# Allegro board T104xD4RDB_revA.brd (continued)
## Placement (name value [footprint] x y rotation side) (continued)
C1023  0.1uF  [0402]  186.82 169.67 90 top
C1024  0.1uF  [0402]  187.96 160.27 270 top
C1025  0.1uF  [0402]  38.74 35.81 90 top
C1026  0.1uF  [0402]  170.18 142.24 0 top
C1027  0.1uF  [0402]  53.85 61.47 90 top
C1028  0.1uF  [0402]  51.44 52.96 90 top
C1029  0.1uF  [0402]  27.94 146.56 0 top
C1030  0.1uF  [0402]  34.04 148.34 0 top
C1031  4.7uF  [0603]  43.43 148.08 90 top
C1032  0.1uF  [0402]  44.45 143.26 0 top
C1033  0.1uF  [0402]  44.45 144.27 0 top
C1034  0.1uF  [0402]  28.19 44.45 0 top
C1035  10uF  [1206]  258.7 200.53 0 top
C1036  10uF  [1206]  258.7 171.96 0 top
C1037  10uF  [1206]  258.7 181.48 0 top
C1038  10uF  [1206]  258.7 191.01 0 top
C1039  10uF  [1206]  67.18 82.42 0 top
C1040  0.1uF  [0603]  63.12 81.91 180 top
C1041  100uF  [CAPE_B6D3]  20.57 49.91 90 top
C1042  10uF  [1206]  18.16 43.43 270 top
C1043  330uF  [CAPE_B8]  22.1 61.59 0 top
C1044  330uF  [CAPE_B8]  22.1 70.74 0 top
C1045  10uF  [0805]  6.22 39.75 180 top
C1046  0.1uF  [0402]  12.07 21.72 0 top
C1047  0.1uF  [0402]  14.48 22.73 0 top
C1048  0.1uF  [0402]  20.19 55.37 0 top
C1049  0.1uF  [0402]  5.59 24.26 0 top
C1050  0.1uF  [0402]  6.6 32.64 0 top
C1051  0.1uF  [0402]  7.62 26.16 270 top
C1052  0.1uF  [0402]  8.13 27.69 0 top
C1053  10uF  [0805]  9.14 25.4 270 top
C1054  0.1uF  [0402]  195.07 100.2 0 top
C1055  0.1uF  [0402]  195.07 101.47 0 top
C1065  22uF  [0805]  144.78 138.81 90 bottom
C1066  22uF  [0805]  151.13 138.81 90 bottom
C1067  0.1uF  [0402]  144.4 68.96 0 top
C1068  0.1uF  [0402]  139.7 68.2 270 top
C1069  0.1uF  [0402]  254.64 61.72 90 top
C1070  0.01uF  [0402]  242.57 38.1 270 top
C1071  0.1uF  [0402]  253.75 38.1 90 top
C1072  0.01uF  [0402]  251.46 38.1 270 top
C1073  0.01uF  [0402]  248.41 38.1 270 top
C1074  0.01uF  [0402]  245.49 38.1 270 top
C1075  1000pF  [1206]  240.67 20.7 90 bottom
C1076  0.1uF  [0402]  251.84 41.91 0 top
C1077  0.1uF  [0402]  251.84 42.93 0 top
C1078  1000pF  [1206]  251.33 28.19 270 bottom
C1079  470pF  [0402]  237.87 52.07 270 top
C1080  470pF  [0402]  236.86 54.1 270 top
C1081  1000pF  [1206]  240.67 28.19 270 bottom
C1082  4.7pF  [0402]  240.79 49.02 180 top
C1083  4.7pF  [0402]  240.79 48.01 180 top
C1084  1000pF  [0402]  239.65 44.58 180 bottom
C1085  22uF  [0805]  240.41 43.05 180 bottom
C1086  0.1uF  [0402]  238.76 43.43 90 top
C1087  0.1uF  [0402]  251.33 54.61 270 bottom
C1088  0.1uF  [0402]  244.48 54.99 0 bottom
C1089  0.1uF  [0402]  242.7 48.39 0 bottom
C1090  0.1uF  [0402]  253.24 46.86 90 bottom
C1091  0.1uF  [0402]  249.94 54.61 270 bottom
C1092  0.1uF  [0402]  249.81 46.86 90 bottom
C1093  0.1uF  [0402]  248.29 46.86 90 bottom
C1094  0.1uF  [0402]  244.98 46.86 90 bottom
C1095  0.1uF  [0402]  244.48 49.78 0 bottom
C1096  0.1uF  [0402]  251.71 46.86 90 bottom
C1097  0.1uF  [0402]  247.02 46.86 90 bottom
C1098  22uF  [0805]  240.16 46.35 180 top
C1099  0.1uF  [0402]  243.46 46.99 0 bottom
C1100  0.1uF  [0402]  246 46.86 90 bottom
C1101  0.1uF  [0402]  242.95 54.86 90 bottom
C1102  0.1uF  [0402]  252.6 52.58 180 bottom
C1103  0.1uF  [0402]  252.6 50.16 180 bottom
C1104  0.01uF  [0402]  266.83 38.1 270 top
C1105  0.1uF  [0402]  272.03 38.1 90 top
C1106  0.01uF  [0402]  269.88 38.1 270 top
C1107  0.01uF  [0402]  260.99 38.1 270 top
C1108  0.01uF  [0402]  263.91 38.1 270 top
C1109  1000pF  [1206]  259.08 20.7 90 bottom
C1110  0.1uF  [0402]  274.7 41.91 0 top
C1111  0.1uF  [0402]  274.7 42.93 0 top
C1112  1000pF  [1206]  259.08 28.19 270 bottom
C1113  470pF  [0402]  260.73 52.07 270 top
C1114  470pF  [0402]  259.72 54.1 270 top
C1115  1000pF  [1206]  269.75 28.19 270 bottom
C1116  4.7pF  [0402]  263.65 49.02 180 top
C1117  4.7pF  [0402]  263.65 48.01 180 top
C1118  1000pF  [0402]  262.51 44.58 180 bottom
C1119  22uF  [0805]  263.27 43.05 180 bottom
C1120  0.1uF  [0402]  272.67 46.86 90 bottom
C1121  0.1uF  [0402]  274.19 54.61 270 bottom
C1122  0.1uF  [0402]  267.34 54.99 0 bottom
C1123  0.1uF  [0402]  265.81 54.86 90 bottom
C1124  0.1uF  [0402]  276.1 46.86 90 bottom
C1125  0.1uF  [0402]  272.8 54.61 270 bottom
C1126  0.1uF  [0402]  267.34 49.78 0 bottom
C1127  0.1uF  [0402]  274.57 46.86 90 bottom
C1128  0.1uF  [0402]  261.62 43.43 90 top
C1129  0.1uF  [0402]  271.14 46.86 90 bottom
C1130  0.1uF  [0402]  269.88 46.86 90 bottom
C1131  0.1uF  [0402]  267.84 46.86 90 bottom
C1132  22uF  [0805]  263.02 46.35 180 top
C1133  0.1uF  [0402]  265.56 48.39 0 bottom
C1134  0.1uF  [0402]  266.32 46.99 0 bottom
C1135  0.1uF  [0402]  268.86 46.86 90 bottom
C1136  0.1uF  [0402]  275.46 50.16 180 bottom
C1137  0.1uF  [0402]  275.46 52.58 180 bottom
C1138  3000pF  [0402]  129.92 89.92 180 bottom
D1  GRN  [LED_0603]  91.95 77.47 0 top
D2  CMHD3595  [SOD123]  57.79 25.4 90 top
D3  CMHD3595  [SOD123]  66.93 31.24 0 top
D4  GRN  [LED_0603]  80.14 22.61 90 top
D5  GRN  [LED_PM_1S]  36.45 1.14 0 top
D6  GRN  [LED_PM_1S]  32.13 1.14 0 top
D7  RB521  [SOD523]  5.84 21.97 0 top
F1  1A  [1206]  19.18 38.23 270 top
F2  500mA  [1206]  258.7 195.83 0 top
F3  500mA  [1206]  258.7 176.78 0 top
F4  500mA  [1206]  258.7 186.31 0 top
F5  500mA  [1206]  258.7 205.36 0 top
FB1  BLM21PG121SN1  [0805]  66.8 19.56 90 top
FB2  BLM21PG121SN1  [0805]  75.44 20.45 90 top
FB3  BLM21PG121SN1  [0805]  64.77 20.07 90 top
FB4  BLM21PG121SN1  [0805]  73.41 19.94 90 top
FB5  BLM18PG121SN1  [0603]  130.3 85.85 270 bottom
FB6  BLM18PG121SN1  [0603]  128.14 86.61 0 bottom
FB7  BLM18PG121SN1  [0603]  125.22 86.61 180 bottom
FB8  BLM18BD601SN1  [0603]  105.54 28.32 0 top
FB9  BLM18BD601SN1  [0603]  105.54 25.53 0 top
FB10  BLM18BD601SN1  [0603]  105.54 26.92 0 top
FB11  BLM18BD601SN1  [0603]  105.54 29.72 0 top
FB12  BLM18BD601SN1  [0603]  105.54 24.13 0 top
FB13  BLM18BD601SN1  [0603]  105.54 21.34 0 top
FB14  BLM18BD601SN1  [0603]  105.54 22.73 0 top
FB15  BLM18BD601SN1  [0603]  105.54 31.11 0 top
FB16  BLM18PG121SN1  [0603]  97.03 29.21 90 top
FB17  BLM18PG121SN1  [0603]  88.52 31.5 180 bottom
FB18  BLM18PG121SN1  [0603]  68.45 58.29 0 bottom
FB20  BLM18BD601SN1  [0603]  150.88 37.97 270 top
FB21  BLM18BD601SN1  [0603]  153.42 38.48 0 top
FB22  BLM18PG121SN1  [0603]  179.58 90.04 90 top
FB23  BLM18PG121SN1  [0603]  177.67 83.69 90 top
FB24  BLM18PG121SN1  [0603]  211.33 90.04 90 top
FB25  BLM18PG121SN1  [0603]  209.42 83.69 90 top
FB26  BLM18BD601SN1  [0603]  239.01 60.71 180 top
FB37  BLM18BD601SN1  [0603]  28.19 129.29 0 top
FB38  BLM18BD601SN1  [0603]  28.19 137.41 0 top
FB39  BLM18BD601SN1  [0603]  28.19 121.16 0 top
FB40  BLM18BD601SN1  [0603]  25.02 100.71 180 top
FB41  BLM18BD601SN1  [0603]  204.47 102.62 180 top
FB42  BLM18PG221SN1  [0603]  235.08 128.4 270 bottom
FB43  BLM18PG221SN1  [0603]  235.08 125.48 270 bottom
FB44  BLM18BD601SN1  [0603]  255.02 38.61 270 top
FB45  BLM18BD601SN1  [0603]  273.43 38.35 270 top
FB46  BLM18PG121SN1  [0603]  95.38 17.91 270 top
J1  DDR4_DIMM  [CON_DDR4_DIMM]  130.05 164.97 0 top
J2  JMP3  [JMP_P254_T_1X3]  20.7 28.83 180 top
J3  SD_CARD_SKT  [CON_SD]  39.02 2.52 180 bottom
J4  HTST-108-01-L-DV  [HDR_P254_HTST_2X8]  10.54 117.35 0 top
J5  USB_A_2  [CON_USB_A_2]  69.02 -0.98 0 top
J6  JMP2  [JMP_P254_T_1X2]  65.91 145.8 270 top
J7  JMP2  [JMP_P254_T_1X2]  65.91 142.62 270 top
J8  JMP2  [JMP_P254_T_1X2]  65.91 148.97 270 top
J9  2XDB9  [DUALDB-9MM]  110.86 16.02 0 top
J10  BAT_SOCKET  [CON_BAT_WBA3B2]  56.01 155.7 180 top
J11  CONN_2X20  [CON_MEC6_120]  277.88 152.06 0 top
J12  HDMI_A  [CON_HDMI]  88.02 -0.98 0 top
J13  DF14-20P-1.25H  [CON_FPC_DF14_20P]  41.4 19.56 180 top
J14  HDR_1X2  [JMP_P254_T_1X2]  17.15 24.26 0 top
J15  HDR_1X2  [JMP_P254_T_1X2]  20.83 24.26 0 top
J16  CON_3PIN  [CON_WAFER_P254_S_1X3]  13.59 37.97 0 top
J17  CON_3PIN  [CON_WAFER_P254_S_1X3]  13.59 30.99 0 top
J18  JMP2  [JMP_P254_T_1X2]  249.94 171.83 270 top
J19  RJ45_LED_2X1  [CON_RJ45_2X1_LED]  142.86 -1.48 0 top
J20  RJ45_LED  [CON_RJ45_UP_1X1_LED]  161.36 -1.48 0 top
J21  RJ45_LED_8  [CON_RJ45_2X4_LED]  203.36 -1.48 0 top
J26  PCIE_X1  [CON_PEX1]  277.88 93.73 90 top
J27  MINIPCIE_CONN  [CON_MINIPCIE]  209.3 183.9 180 top
J28  MINIPCIE_CONN  [CON_MINIPCIE]  82.3 183.9 180 top
J29  SATA_CONN  [CON_SATA]  195.45 129.67 270 top
J30  CONN SKT 70  [CON2X35_SKT_0P8_SM]  225.17 143.64 90 top
J31  HDR_2X5  [HDR_P254_M_T_2X5]  24.38 83.19 180 top
J32  CON_3PIN  [CON_WAFER_P254_S_1X3]  264.54 193.42 90 top
J33  CON_3PIN  [CON_WAFER_P254_S_1X3]  264.54 174.37 90 top
J34  CON_3PIN  [CON_WAFER_P254_S_1X3]  264.54 183.9 90 top
J35  CON_3PIN  [CON_WAFER_P254_S_1X3]  264.54 202.95 90 top
J36  CON_3PIN  [CON_WAFER_P254_S_1X3]  64.01 77.34 180 top
J37  ATX_PWR_CONN_20PIN  [CON_ATX_20PIN]  10.54 63.88 270 top
J38  HDR_1X2  [JMP_P254_T_1X2]  20.07 17.02 0 top
J39  HDR_1X2  [JMP_P254_T_1X2]  15.75 17.02 0 top
J40  RJ45_LED  [CON_RJ45_UP_1X1_LED]  245.36 -1.48 0 top
J41  RJ45_LED  [CON_RJ45_UP_1X1_LED]  263.86 -1.48 0 top
J42  HDR_1X5  [HDR_P254_M_T_1X5]  244.09 165.48 90 top
L1  90ohm  [IND_CM_2012]  71.25 20.95 270 top
L2  90ohm  [IND_CM_2012]  68.96 20.95 270 top
L3  10uH  [0806]  240.54 165.74 0 top
L4  2.2uH  [IND_SWPA2520]  119.25 45.85 180 top
L5  2.2uH  [IND_SWPA2520]  137.16 53.85 180 top
L6  4.7uH  [IND_SWPA2520]  155.07 41.78 270 top
L7  1.0uH  [IND_IHLP_4040]  80.77 97.03 0 top
L9  2.2uH  [IND_IHLP_2525]  180.21 145.41 180 top
L10  3.3uH  [IND_IHLP_2525]  31.75 169.55 90 top
L11  3.3uH  [IND_IHLP_2525]  43.57 60.96 0 top
L12  4.7uH  [IND_IHLP_2525]  244.73 66.92 270 top
L13  2.2uH  [IND_IHLP_2525]  42.04 49.78 0 top
L15  2.2uH  [IND_IHLP_2525]  239.77 89.66 180 top
L17  4.7uH  [IND_SWPA2520]  240.67 43.69 270 top
L18  4.7uH  [IND_SWPA2520]  263.52 43.69 270 top
L19  90ohm  [IND_CM_2012]  92.58 14.35 270 top
L20  90ohm  [IND_CM_2012]  90.42 14.22 270 top
L21  90ohm  [IND_CM_2012]  88.27 14.22 270 top
L22  90ohm  [IND_CM_2012]  86.11 14.86 270 top
M2  MH  [MH_580S340P]  70.2 207.8 0 top
M3  MH  [MH_580S340P]  94.4 207.8 0 top
M4  MH  [MH_580S340P]  197.2 207.8 0 top
M5  MH  [MH_580S340P]  221.4 207.8 0 top
NOREF  val  [unnamed]  134.37 102.62 90 top
NOREF#2  -  [#2]  -252.98 -202.18 0 top
Q2  IRLML6346  [SOT23]  243.33 123.44 0 top
Q3  IRLML6346  [SOT23]  245.36 126.36 90 top
Q4  IRLML6346  [SOT23]  70.87 34.8 0 top
Q5  IRLML6346  [SOT23]  67.06 36.96 0 top
Q6  IRLML6346  [SOT23]  23.75 14.35 180 top
Q7  IRFH6200  [SO_8_FL]  93.85 105.28 270 bottom
Q8  IRLML6346  [SOT23]  93.85 104.9 270 top
Q9  IRFHM4226  [U8_FL]  35.05 36.83 0 top
Q10  IRFH6200  [SO_8_FL]  172.47 146.94 270 top
Q11  IRFHM4226  [U8_FL]  50.04 59.69 90 top
Q12  IRLML6346  [SOT23]  39.5 38.86 90 top
Q13  IRLML6346  [SOT23]  172.09 140.59 0 top
Q14  IRLML6346  [SOT23]  51.05 63.75 270 top
Q15  IRFH6200  [SO_8_FL]  49.78 48.77 90 top
Q16  IRLML2030  [SOT23]  36.96 144.4 0 top
Q17  IRLML2030  [SOT23]  40.64 144.4 0 top
Q18  IRLML6346  [SOT23]  48.9 53.85 270 top
Q19  IRLML2030  [SOT23]  40.64 148.46 0 top
Q20  IRLML2030  [SOT23]  36.96 148.46 0 top
Q21  IRLML6346  [SOT23]  32 144.53 270 top
Q22  IRLML6346  [SOT23]  31.12 148.46 0 top
Q23  IRF9321  [SO_8]  25.65 38.61 270 top
Q24  IRLML6346  [SOT23]  30.35 41.78 180 top
Q25  IRLML6346  [SOT23]  113.03 156.97 0 bottom
Q26  IRLML6346  [SOT23]  116.71 156.97 0 bottom
Q27  TP0610K  [SOT23]  63.25 84.45 270 top
Q28  IRLML6346  [SOT23]  58.17 83.82 0 top
Q29  MMBT4401  [SOT23]  6.22 35.18 0 top
Q30  IRFHM4226  [U8_FL]  250.83 62.74 0 top
Q31  IRLML6346  [SOT23]  255.02 64.9 270 top
R1  162  [0402]  136.77 114.32 270 bottom
R2  162  [0402]  133.57 114.32 270 bottom
R3  10K  [0402]  127.16 114.32 270 bottom
R4  0  [0402]  125.6 104.9 0 bottom
R5  1K  [0402]  109.47 160.27 90 top
R6  20K  [0402]  63.75 129.79 270 bottom
R7  20K  [0402]  65.02 129.79 270 bottom
R8  20K  [0402]  61.21 129.79 270 bottom
R9  4.7K  [0402]  58.55 130.56 270 bottom
R10  4.7K  [0402]  57.53 130.56 270 bottom
R11  4.7K  [0402]  54.48 130.56 270 bottom
R12  4.7K  [0402]  56.52 130.56 270 bottom
R13  20K  [0402]  62.48 129.79 270 bottom
R14  4.7K  [0402]  118.49 101.47 270 bottom
R15  4.7K  [0402]  55.5 130.56 270 bottom
R16  20K  [0402]  81.41 117.6 0 bottom
R17  20K  [0402]  67.56 129.79 90 bottom
R18  20K  [0402]  73.91 129.79 90 bottom
R19  20K  [0402]  72.64 129.79 90 bottom
R20  20K  [0402]  71.37 129.79 90 bottom
R21  22  [0402]  121.67 104.14 180 bottom
R22  4.7K  [0402]  81.41 116.59 0 bottom
R23  33  [0402]  91.31 113.92 180 bottom
R24  33  [0402]  91.31 114.94 180 bottom
R25  33  [0402]  89.28 115.44 180 bottom
R26  33  [0402]  91.31 115.95 180 bottom
R27  33  [0402]  91.31 116.97 180 bottom
R28  33  [0402]  89.28 117.47 180 bottom
R29  33  [0402]  91.31 117.98 180 bottom
R30  33  [0402]  89.28 118.49 180 bottom
R31  4.7K  [0402]  45.97 135.13 270 bottom
R32  33  [0402]  91.31 119 180 bottom
R33  4.7K  [0402]  47.24 135.13 270 bottom
R34  33  [0402]  91.31 120.02 180 bottom
R35  4.7K  [0402]  48.51 135.13 270 bottom
R36  33  [0402]  91.31 121.03 180 bottom
R37  4.7K  [0402]  49.78 135.13 270 bottom
R38  4.7K  [0402]  51.05 135.13 270 bottom
R39  4.7K  [0402]  52.32 135.13 270 bottom
R40  4.7K  [0402]  53.59 135.13 270 bottom
R41  4.7K  [0402]  54.86 135.13 270 bottom
R42  4.7K  [0402]  58.67 135.13 270 bottom
R43  4.7K  [0402]  59.94 135.13 270 bottom
R44  4.7K  [0402]  61.21 135.13 270 bottom
R45  4.7K  [0402]  62.48 135.13 270 bottom
R46  4.7K  [0402]  63.75 135.13 270 bottom
R47  4.7K  [0402]  66.29 135.13 270 bottom
R48  4.7K  [0402]  65.02 135.13 270 bottom
R49  4.7K  [0402]  67.56 135.13 270 bottom
R50  4.7K  [0402]  73.53 126.75 90 bottom
R51  4.7K  [0402]  86.87 121.79 180 bottom
R52  4.7K  [0402]  72.52 116.46 0 bottom
R53  4.7K  [0402]  64.77 125.22 0 bottom
R54  1K  [0402]  86.87 122.81 180 bottom
R55  4.7K  [0402]  86.87 120.78 180 bottom
R56  1K  [0402]  64.77 124.21 0 bottom
R57  4.7K  [0402]  267.34 145.16 180 top
R58  4.7K  [0402]  268.86 148.72 90 top
R59  4.7K  [0402]  257.56 145.29 0 top
R60  4.7K  [0402]  258.83 159 0 top
R61  33  [0402]  268.35 147.19 180 top
R62  4.7K  [0402]  270.76 148.21 180 top
R63  4.7K  [0402]  270.76 149.22 180 top
R64  51  [0402]  268.35 146.18 180 top
R65  10  [0402]  133.29 87.38 270 bottom
R66  51  [0402]  267.84 148.72 270 top
R67  0  [0402]  131.45 89.41 270 bottom
R68  10K  [0402]  32.13 38.23 90 bottom
R69  10K  [0402]  33.15 38.23 90 bottom
R70  10K  [0402]  46.1 38.23 90 bottom
R71  10K  [0402]  45.09 38.23 90 bottom
R72  10K  [0402]  34.16 38.23 90 bottom
R73  10K  [0402]  44.07 38.23 90 bottom
R74  10K  [0402]  43.05 38.23 90 bottom
R75  10K  [0402]  31.12 38.23 90 bottom
R78  4.7K  [0402]  52.96 101.22 0 bottom
R79  4.7K  [0402]  52.96 100.2 0 bottom
R80  4.7K  [0402]  121.54 95 180 bottom
R81  4.7K  [0402]  55.12 91.82 0 bottom
R82  4.7K  [0402]  121.54 91.95 180 bottom
R83  4.7K  [0402]  121.54 92.96 180 bottom
R84  4.7K  [0402]  139.32 90.17 270 bottom
R85  4.7K  [0402]  139.83 88.65 180 bottom
R86  4.7K  [0402]  140.34 90.17 270 bottom
R87  4.7K  [0402]  140.84 87.63 180 bottom
R88  4.7K  [0402]  133.41 89.41 270 bottom
R89  4.7K  [0402]  136.27 89.41 270 bottom
R90  4.7K  [0402]  55.12 94.87 0 bottom
R91  4.7K  [0402]  121.67 105.16 180 bottom
R92  1K  [0402]  54.48 99.95 90 bottom
R93  1K  [0402]  121.54 93.98 180 bottom
R94  4.7K  [0402]  55.12 92.84 0 bottom
R95  4.7K  [0402]  56.64 93.85 90 bottom
R96  4.7K  [0402]  248.54 126.24 0 top
R97  4.7K  [0402]  246.25 123.95 0 top
R98  4.7K  [0402]  248.54 127.25 0 top
R99  4.7K  [0402]  246.25 122.94 0 top
R100  4.7K  [0402]  137.29 89.41 270 bottom
R101  4.7K  [0402]  219.58 168.53 0 top
R102  4.7K  [0402]  138.3 89.41 270 bottom
R103  4.7K  [0402]  219.58 167.51 0 top
R104  4.7K  [0402]  48.01 102.62 180 bottom
R105  4.7K  [0402]  53.09 98.68 270 bottom
R106  4.7K  [0402]  55.12 93.85 180 bottom
R107  4.7K  [0402]  229.87 167.89 90 top
R108  4.7K  [0402]  134.37 89.41 90 bottom
R109  4.7K  [0402]  135.32 89.41 90 bottom
R110  4.7K  [0402]  97.79 77.41 270 top
R111  4.7K  [0402]  56.9 128.52 180 bottom
R112  510  [0402]  92.58 78.87 180 top
R113  698  [0402]  121.67 107.19 0 bottom
R114  698  [0402]  121.67 106.17 0 bottom
R115  10K  [0402]  97.54 126.75 0 top
R116  10  [0402]  18.92 112.27 0 top
R117  10K  [0402]  18.92 114.81 0 top
R118  10K  [0402]  18.92 113.54 180 top
R119  10K  [0402]  18.92 111 180 top
R120  10K  [0402]  18.92 108.58 180 top
R121  10K  [0402]  18.92 105.92 180 top
R122  10K  [0402]  18.92 103.38 180 top
R123  10K  [0402]  18.92 100.84 180 top
R124  10  [0402]  147.57 94.87 0 bottom
R125  10  [0402]  144.4 90.17 90 bottom
R126  10  [0402]  149.61 95.38 0 bottom
R127  10  [0402]  142.37 90.17 90 bottom
R128  10  [0402]  149.61 94.36 0 bottom
R129  10  [0402]  141.35 89.66 90 bottom
R130  10  [0402]  147.57 93.85 0 bottom
R131  4.7K  [0402]  146.81 92.08 0 bottom
R132  10  [0402]  145.92 89.92 0 bottom
R133  10  [0402]  143.38 90.17 90 bottom
R134  4.7K  [0402]  147.57 97.54 180 bottom
R135  10  [0402]  147.45 90.55 90 bottom
R136  10  [0402]  149.61 97.54 0 bottom
R137  10  [0402]  149.61 96.39 0 bottom
R138  10  [0402]  149.61 93.34 180 bottom
R139  1.5K  [0402]  124.97 57.91 270 top
R140  4.7K  [0402]  125.98 58.17 270 top
R142  4.7K  [0402]  155.58 95 180 bottom
R143  4.7K  [0402]  155.58 93.98 180 bottom
R144  4.7K  [0402]  155.58 92.96 180 bottom
R145  200  [0402]  140.77 99.81 270 bottom
R146  698  [0402]  148.08 109.73 180 bottom
R147  4.7K  [0402]  213.11 102.23 0 top
R148  4.7K  [0402]  219.71 118.11 0 top
R149  10K  [0402]  69.85 38.35 0 top
R150  10K  [0402]  69.85 37.34 0 top
R151  0  [0402]  65.41 33.4 0 top
R152  100K  [0402]  67.69 34.42 0 top
R153  100K  [0402]  67.69 33.4 0 top
R154  51.1K  [0402]  57.79 28.45 0 top
R155  0  [0402]  65.41 34.42 0 top
R156  1K  [0402]  61.34 37.47 270 top
R157  1K  [0402]  63.37 37.47 270 top
R158  51.1K  [0402]  69.98 31.24 90 top
R159  26.7K  [0402]  62.36 37.47 270 top
R160  18.2K  [0402]  57.79 29.46 180 top
R161  18.2K  [0402]  70.99 31.24 270 top
R162  0  [0402]  71.76 21.08 270 top
R163  0  [0402]  70.74 21.08 270 top
R164  0  [0402]  69.47 21.08 270 top
R165  0  [0402]  68.45 21.08 270 top
R166  10K  [0402]  123.57 89.92 0 bottom
R167  49.9  [0402]  123.57 87.88 0 bottom
R168  49.9  [0402]  122.56 90.93 0 bottom
R169  49.9  [0402]  122.05 89.41 270 bottom
R170  0  [0402]  132.4 89.41 270 bottom
R171  330  [0402]  68.2 145.67 90 top
R172  330  [0402]  68.2 142.49 90 top
R173  330  [0402]  68.2 148.84 90 top
R174  5.1  [0402]  121.41 97.92 0 bottom
R175  0.33  [0402]  159.13 112.65 0 bottom
R176  0  [0402]  159.13 113.66 0 bottom
R177  5.1  [0402]  121.41 100.46 0 bottom
R178  0.33  [0402]  159.13 116.46 0 bottom
R179  0  [0402]  159.13 117.47 0 bottom
R180  5.1  [0402]  120.02 94.49 90 bottom
R181  5.1  [0402]  117.6 106.68 90 bottom
R182  100  [0402]  102.87 28.32 0 top
R183  100  [0402]  102.87 25.53 0 top
R184  100  [0402]  102.87 26.92 0 top
R185  100  [0402]  102.87 29.72 0 top
R186  100  [0402]  102.87 24.13 0 top
R187  100  [0402]  102.87 21.34 0 top
R188  100  [0402]  102.87 22.73 0 top
R189  100  [0402]  103.38 31.62 270 top
R190  4.7K  [0402]  56.39 147.45 0 top
R191  1K  [0402]  51.31 149.61 0 top
R192  4.7K  [0402]  112.27 112.01 90 bottom
R193  100  [0402]  118.62 109.6 180 bottom
R194  100  [0402]  118.62 108.58 180 bottom
R195  4.7K  [0402]  113.28 112.01 90 bottom
R196  4.7K  [0402]  270.76 144.78 0 top
R197  4.7K  [0402]  270.76 143.76 0 top
R198  4.7K  [0402]  270.76 142.75 0 top
R199  4.7K  [0402]  270.76 141.73 0 top
R200  51  [0402]  270.76 150.24 180 top
R201  33  [0402]  270.76 147.19 180 top
R202  51  [0402]  270.76 146.18 180 top
R203  4.7K  [0402]  84.2 13.21 90 top
R204  4.7K  [0402]  84.2 15.49 270 top
R205  49.9K  [0402]  85.73 26.92 90 top
R206  49.9K  [0402]  83.69 26.92 90 top
R207  49.9K  [0402]  82.68 26.92 90 top
R208  49.9K  [0402]  84.71 26.92 90 top
R209  49.9K  [0402]  81.28 38.73 0 top
R210  0  [0402]  82.17 25.4 0 top
R211  49.9K  [0402]  81.28 36.7 0 top
R212  140  [0402]  97.28 34.29 90 top
R213  2.37K  [0402]  86.74 26.92 270 top
R214  1K  [0402]  91.06 39.12 180 bottom
R215  15K  [0402]  83.19 15.49 90 top
R216  4.7K  [0402]  81.28 35.69 0 top
R217  4.7K  [0402]  81.28 32.89 0 top
R218  1K  [0402]  91.06 38.1 180 bottom
R219  0  [0402]  81.28 34.42 0 top
R220  330  [0402]  81.66 23.88 270 top
R221  4.7K  [0402]  64.26 58.67 90 top
R222  4.7K  [0402]  63.25 58.67 90 top
R223  49.9K  [0402]  77.72 43.43 270 top
R224  4.7K  [0402]  18.03 26.42 180 top
R225  49.9K  [0402]  78.23 47.75 180 top
R226  0  [0402]  78.23 48.77 180 top
R227  4.7K  [0402]  20.19 26.42 180 top
R228  49.9K  [0402]  68.33 58.67 270 top
R229  4.7K  [0402]  66.29 58.67 270 top
R230  4.7K  [0402]  65.28 58.67 270 top
R231  4.7K  [0402]  62.23 58.67 270 top
R232  4.7K  [0402]  61.21 58.67 270 top
R233  0  [1206]  19.18 38.23 270 top
R234  4.7K  [0402]  18.54 33.53 270 top
R235  4.7K  [0402]  18.54 31.5 270 top
R236  0  [1206]  237.49 167.13 270 top
R237  270K  [0603]  243.46 161.16 90 top
R238  0  [1206]  234.95 167.13 270 top
R239  4.7K  [0402]  96.77 46.61 270 bottom
R240  4.7K  [0402]  103.63 54.36 270 bottom
R241  4.7K  [0402]  251.46 144.78 270 top
R242  0  [1206]  246.89 161.42 180 top
R243  100  [1206]  250.57 168.78 0 top
R244  0  [1206]  252.35 161.42 180 top
R245  4.7K  [0402]  247.65 145.29 0 top
R246  4.7K  [0402]  249.68 145.29 180 top
R247  75  [0603]  122.3 26.03 90 bottom
R248  75  [0603]  125.35 26.03 90 bottom
R249  75  [0603]  128.27 26.03 90 bottom
R250  33  [0402]  132.84 50.93 180 top
R251  33  [0402]  130.43 46.86 180 top
R252  75  [0603]  131.32 26.03 90 bottom
R253  33  [0402]  130.43 47.88 180 top
R254  33  [0402]  130.43 48.9 180 top
R255  33  [0402]  130.43 49.91 180 top
R256  33  [0402]  130.43 45.85 180 top
R258  33  [0402]  117.48 47.88 180 top
R259  510  [0402]  122.94 56.13 90 top
R260  510  [0402]  120.02 55.37 180 top
R262  0  [0402]  130.81 51.94 0 top
R263  0  [0402]  120.4 52.2 270 top
R264  0  [0402]  123.95 54.48 90 top
R265  4.7K  [0402]  125.86 54.61 270 top
R266  15  [0402]  119.63 46.74 180 bottom
R267  0  [0402]  120.65 51.82 270 bottom
R268  2.49K  [0402]  119.38 52.07 270 top
R269  4.7K  [0402]  132.46 46.86 0 top
R270  4.7K  [0402]  132.46 47.88 0 top
R271  4.7K  [0402]  132.46 48.9 0 top
R272  4.7K  [0402]  132.46 49.91 0 top
R273  4.7K  [0402]  132.46 45.85 0 top
R274  4.7K  [0402]  122.43 54.61 180 top
R275  4.7K  [0402]  120.02 54.36 180 top
R276  4.7K  [0402]  123.95 56.52 90 top
R277  75  [0603]  138.18 29.97 90 bottom
R278  75  [0603]  141.1 29.97 90 bottom
R279  75  [0603]  144.02 29.97 90 bottom
R280  33  [0402]  148.21 54.74 180 top
R281  33  [0402]  150.75 58.8 180 top
R282  75  [0603]  147.07 29.97 90 bottom
R283  33  [0402]  148.21 55.75 180 top
R284  33  [0402]  148.21 56.77 180 top
R285  33  [0402]  148.21 57.78 180 top
R286  33  [0402]  148.21 53.72 180 top
R288  33  [0402]  135.64 55.75 180 top
R289  510  [0402]  140.34 62.61 180 top
R290  510  [0402]  137.8 62.48 90 top
R292  0  [0402]  148.72 59.82 0 top
R293  0  [0402]  138.3 60.2 270 top
R294  0  [0402]  141.86 62.48 90 top
R295  4.7K  [0402]  143.76 62.61 270 top
R296  15  [0402]  138.05 54.23 270 bottom
R297  0  [0402]  138.56 59.94 270 bottom
R298  2.49K  [0402]  137.29 59.94 270 top
R299  4.7K  [0402]  150.24 54.74 0 top
R300  4.7K  [0402]  150.24 55.75 0 top
R301  4.7K  [0402]  150.24 56.77 0 top
R302  4.7K  [0402]  150.24 57.78 0 top
R303  4.7K  [0402]  150.24 53.72 0 top
R304  4.7K  [0402]  140.84 64.13 90 top
R305  4.7K  [0402]  138.81 62.48 90 top
R306  4.7K  [0402]  141.86 64.52 90 top
R307  75  [0603]  157.86 18.29 90 bottom
R308  75  [0603]  160.53 18.29 90 bottom
R309  75  [0603]  163.45 18.29 90 bottom
R310  4.7K  [0402]  169.16 48.9 90 top
R311  4.7K  [0402]  169.16 50.93 90 top
R312  4.7K  [0402]  169.16 52.96 270 top
R313  75  [0603]  166.5 18.29 90 bottom
R314  4.7K  [0402]  165.99 55.24 270 top
R315  4.7K  [0402]  167.51 54.74 180 top
R316  510  [0402]  152.78 52.7 180 top
R317  510  [0402]  152.78 51.69 180 top
R318  4.7K  [0402]  155.19 51.18 180 top
R319  4.7K  [0402]  155.19 52.2 0 top
R320  4.7K  [0402]  153.29 50.16 270 top
R321  4.7K  [0402]  155.19 53.21 0 top
R323  0  [0402]  155.19 50.16 180 top
R324  0  [0402]  155.19 49.15 0 top
R325  4.7K  [0402]  163.83 54.74 180 top
R326  15  [0402]  156.08 42.67 180 bottom
R327  2.49K  [0402]  155.19 48.13 0 top
R328  12.1K  [0402]  169.16 45.47 270 top
R329  0  [0402]  158.37 51.56 270 bottom
R330  4.7K  [0402]  199.26 88.39 0 top
R331  0  [0402]  197.23 88.39 0 top
R333  4.7K  [0402]  179.45 83.44 180 top
R334  4.7K  [0402]  179.45 84.45 180 top
R335  4.7K  [0402]  179.45 82.42 180 top
R336  4.7K  [0402]  199.26 86.36 180 top
R337  4.7K  [0402]  193.29 86.61 180 bottom
R338  619  [0402]  184.4 92.08 180 top
R339  1K  [0402]  197.23 87.38 180 top
R340  2K  [0402]  188.34 74.68 90 top
R341  4.7K  [0402]  231.01 88.39 0 top
R342  0  [0402]  228.98 88.39 0 top
R344  4.7K  [0402]  211.2 83.44 180 top
R345  4.7K  [0402]  211.2 84.45 180 top
R346  4.7K  [0402]  211.2 82.42 180 top
R347  4.7K  [0402]  231.01 86.36 180 top
R348  4.7K  [0402]  225.04 86.61 180 bottom
R349  619  [0402]  216.15 92.08 180 top
R350  1K  [0402]  228.98 87.38 180 top
R351  2K  [0402]  220.09 74.68 90 top
R352  75  [0603]  217.3 32.13 90 bottom
R353  75  [0603]  185.55 32.13 90 bottom
R354  75  [0603]  214.25 32.13 90 bottom
R355  75  [0603]  182.5 32.13 90 bottom
R356  75  [0603]  211.33 32.13 90 bottom
R357  75  [0603]  179.58 32.13 90 bottom
R358  75  [0603]  208.41 32.13 90 bottom
R359  75  [0603]  176.66 32.13 90 bottom
R360  510  [0402]  229.62 81.15 0 top
R361  510  [0402]  197.87 81.15 0 top
R362  510  [0402]  229.62 82.17 0 top
R363  510  [0402]  197.87 82.17 0 top
R364  75  [0603]  217.3 53.72 90 bottom
R365  75  [0603]  185.55 53.72 90 bottom
R366  75  [0603]  214.25 53.72 90 bottom
R367  75  [0603]  182.5 53.72 90 bottom
R368  75  [0603]  211.33 53.72 90 bottom
R369  75  [0603]  179.58 53.72 90 bottom
R370  75  [0603]  208.41 53.72 90 bottom
R371  75  [0603]  176.66 53.72 90 bottom
R372  510  [0402]  224.28 83.44 0 bottom
R373  510  [0402]  192.53 83.44 0 bottom
R374  510  [0402]  229.62 80.14 0 top
R375  510  [0402]  197.87 80.14 0 top
R376  75  [0603]  233.17 32.13 90 bottom
R377  75  [0603]  201.42 32.13 90 bottom
R378  75  [0603]  230.12 32.13 90 bottom
R379  75  [0603]  198.37 32.13 90 bottom
R380  75  [0603]  227.2 32.13 90 bottom
R381  75  [0603]  195.45 32.13 90 bottom
R382  75  [0603]  224.28 32.13 90 bottom
R383  75  [0603]  192.53 32.13 90 bottom
R384  510  [0402]  229.62 85.22 0 top
R385  510  [0402]  197.87 85.22 0 top
R386  510  [0402]  225.68 84.45 0 bottom
R387  510  [0402]  193.93 84.45 0 bottom
R388  75  [0603]  233.17 53.72 90 bottom
R389  75  [0603]  230.12 53.72 90 bottom
R390  75  [0603]  201.42 53.72 90 bottom
R391  75  [0603]  198.37 53.72 90 bottom
R392  75  [0603]  227.2 53.72 90 bottom
R393  75  [0603]  195.45 53.72 90 bottom
R394  75  [0603]  224.28 53.72 90 bottom
R395  75  [0603]  192.53 53.72 90 bottom
R396  510  [0402]  197.87 83.19 0 top
R397  510  [0402]  197.87 84.2 0 top
R398  510  [0402]  229.62 83.19 0 top
R399  510  [0402]  229.62 84.2 0 top
R442  4.7K  [0402]  212.47 191.01 90 top
R443  4.7K  [0402]  213.49 191.01 90 top
R444  4.7K  [0402]  272.16 94.36 180 top
R445  4.7K  [0402]  272.16 88.77 180 top
R446  4.7K  [0402]  199.26 177.42 0 top
R447  4.7K  [0402]  272.16 84.71 180 top
R448  4.7K  [0402]  272.16 87.76 180 top
R449  4.7K  [0402]  272.16 102.11 180 top
R450  4.7K  [0402]  272.16 85.72 180 top
R451  4.7K  [0402]  272.16 86.74 180 top
R452  4.7K  [0402]  272.16 95.89 180 top
R453  4.7K  [0402]  85.47 190.88 90 top
R454  4.7K  [0402]  86.49 190.88 90 top
R455  4.7K  [0402]  72.52 177.29 0 top
R456  10K  [0402]  219.84 133.35 180 top
R457  10K  [0402]  219.84 132.33 180 top
R458  10K  [0402]  219.84 131.32 180 top
R459  10K  [0402]  219.84 130.3 180 top
R460  10K  [0402]  219.84 138.43 180 top
R461  10K  [0402]  220.22 143.38 90 top
R462  10K  [0402]  219.84 137.41 180 top
R463  10K  [0402]  219.84 136.4 180 top
R464  10K  [0402]  219.84 135.38 180 top
R465  10K  [0402]  219.84 134.37 180 top
R466  1K  [0402]  219.84 129.29 180 top
R467  10  [0402]  217.42 134.87 0 top
R468  10  [0402]  217.42 135.89 0 top
R469  10  [0402]  217.42 136.91 0 top
R470  4.7K  [0402]  28.07 85.09 270 top
R471  10K  [0402]  28.07 88.77 270 top
R472  10K  [0402]  28.07 92.84 90 top
R473  4.7K  [0402]  71.37 135.13 270 bottom
R474  4.7K  [0402]  72.64 135.13 270 bottom
R475  4.7K  [0402]  73.91 135.13 270 bottom
R476  10K  [0402]  75.18 129.79 270 bottom
R477  1K  [0402]  75.18 135.13 270 bottom
R478  10K  [0402]  76.45 129.79 270 bottom
R479  1K  [0402]  76.45 135.13 270 bottom
R480  10K  [0402]  77.72 129.79 270 bottom
R481  1K  [0402]  77.72 135.13 270 bottom
R482  10K  [0402]  78.99 129.79 270 bottom
R483  1K  [0402]  78.99 135.13 270 bottom
R484  33  [0402]  39.37 127.25 0 top
R485  4.7K  [0402]  29.21 116.46 0 top
R486  1K  [0402]  39.37 126.24 0 top
R487  33  [0402]  39.37 135.38 0 top
R488  1K  [0402]  39.37 134.37 0 top
R489  33  [0402]  39.37 119.13 0 top
R490  1K  [0402]  39.37 118.11 0 top
R491  1K  [0402]  22.99 98.3 270 top
R492  33  [0402]  28.58 98.55 270 top
R493  1K  [0402]  199.26 92.33 0 top
R494  150  [0402]  197.49 101.47 0 top
R495  150  [0402]  197.49 100.2 0 top
R496  150  [0402]  197.49 97.92 0 top
R497  150  [0402]  197.49 99.19 0 top
R498  10  [0402]  197.49 94.36 0 top
R499  49.9  [0402]  246.38 128.78 0 top
R500  0  [0402]  244.35 128.78 0 top
R501  0  [0402]  244.35 130.05 0 top
R502  49.9  [0402]  246.38 130.05 0 top
R503  49.9  [0402]  246.38 131.19 180 top
R504  0  [0402]  244.35 132.46 0 top
R505  49.9  [0402]  241.3 137.29 90 top
R506  0  [0402]  241.3 135.25 90 top
R507  0  [0402]  240.03 135.25 90 top
R508  1K  [0402]  244.22 134.11 180 top
R509  49.9  [0402]  238.89 137.29 270 top
R511  0  [0402]  244.35 131.19 0 top
R512  49.9  [0402]  246.38 132.46 180 top
R513  49.9  [0402]  240.03 137.29 90 top
R514  0  [0402]  238.89 135.25 90 top
R515  0  [0402]  237.62 135.25 90 top
R516  49.9  [0402]  232.79 132.46 180 top
R517  49.9  [0402]  237.62 137.29 270 top
R518  0  [0402]  234.82 132.46 180 top
R519  0  [0402]  234.82 131.19 180 top
R520  49.9  [0402]  232.79 131.19 180 top
R521  49.9  [0402]  232.79 130.05 0 top
R522  0  [0402]  234.82 130.05 180 top
R523  1K  [0402]  234.82 127 0 top
R524  0  [0402]  234.82 128.78 180 top
R525  1K  [0402]  241.17 125.73 90 top
R527  49.9  [0402]  232.79 128.78 0 top
R528  1K  [0402]  234.82 125.98 0 top
R532  10  [0402]  238.25 124.59 0 bottom
R533  10  [0402]  241.05 133.1 180 bottom
R534  0.001  [RES_WSL2726]  86.23 87.25 270 top
R535  124K  [0402]  68.07 100.97 270 top
R536  10K  [0402]  65.41 98.42 180 top
R537  1.65K  [0402]  63.37 97.92 270 top
R538  10K  [0402]  67.06 100.97 270 top
R539  10K  [0402]  63.88 96.9 90 bottom
R540  1K  [0402]  96.39 106.43 90 top
R541  10  [0402]  80.9 87.76 0 top
R542  10  [0402]  80.9 86.74 0 top
R543  10K  [0402]  65.41 99.44 0 top
R544  0  [0402]  96.39 104.39 270 top
R545  0  [0402]  67.31 98.55 180 bottom
R546  10K  [0402]  67.31 97.54 180 bottom
R547  10K  [0402]  65.91 94.87 90 top
R548  200  [0402]  64.39 94.36 180 top
R549  10K  [0402]  92.58 107.44 180 top
R550  60.4  [0402]  67.18 92.2 90 top
R551  0  [0402]  66.68 89.79 180 top
R552  1K  [0402]  90.3 105.03 90 top
R553  10K  [0402]  91.31 105.03 90 top
R554  0  [0402]  69.98 88.14 0 top
R555  0  [0402]  69.98 89.15 0 top
R556  0  [0402]  74.55 90.68 180 top
R558  150K  [0402]  189.73 141.48 90 top
R564  10K  [0402]  192.4 144.02 0 top
R565  10K  [0402]  190.75 141.48 90 top
R566  2.05K  [0402]  194.43 144.53 90 top
R567  14K  [0402]  192.4 147.07 0 top
R568  10K  [0402]  193.55 146.18 270 bottom
R570  10K  [0402]  192.4 143 180 top
R572  0  [0402]  190.49 144.02 0 bottom
R574  10K  [0402]  190.49 145.03 0 bottom
R575  187K  [0402]  27.81 160.03 0 top
R576  226K  [0402]  34.04 64.9 270 top
R577  10K  [0402]  30.35 157.36 270 top
R578  10K  [0402]  31.38 62.36 180 top
R579  10K  [0402]  27.81 159.01 0 top
R580  2.21K  [0402]  30.86 155.33 0 top
R581  10K  [0402]  31.37 157.35 90 top
R582  10K  [0402]  33.4 157.36 270 top
R583  10K  [0402]  33.03 64.9 270 top
R584  2.43K  [0402]  29.34 61.85 270 top
R585  10K  [0402]  31.37 61.34 0 top
R586  10K  [0402]  31.38 59.31 180 top
R587  10K  [0402]  29.34 157.36 90 top
R588  10K  [0402]  31.38 63.37 0 top
R589  0  [0402]  30.35 159.27 270 bottom
R590  0  [0402]  33.28 62.36 180 bottom
R591  4.99K  [0402]  31.37 159.27 270 bottom
R592  3.83K  [0402]  33.28 61.34 180 bottom
R593  309K  [0402]  248.67 76.45 180 top
R594  412K  [0402]  32.51 53.72 270 top
R595  10K  [0402]  246.13 79.11 90 top
R596  10K  [0402]  248.67 77.46 180 top
R597  2.55K  [0402]  245.62 81.15 180 top
R598  10K  [0402]  31.5 53.72 270 top
R599  2.32K  [0402]  27.81 50.67 270 top
R600  10K  [0402]  29.85 48.13 180 top
R601  10K  [0402]  245.11 79.12 270 top
R602  10K  [0402]  243.08 79.11 90 top
R603  10K  [0402]  29.85 51.18 180 top
R604  10K  [0402]  29.34 48.64 90 bottom
R605  10K  [0402]  247.14 79.11 270 top
R606  10K  [0402]  29.85 52.2 0 top
R607  0  [0402]  246.13 77.21 90 bottom
R608  0  [0402]  31.75 51.18 180 bottom
R609  2.49K  [0402]  245.11 77.21 90 bottom
R610  1.78K  [0402]  31.75 50.16 180 bottom
R611  124K  [0402]  249.29 85.72 90 top
R613  10K  [0402]  251.96 88.27 0 top
R615  10K  [0402]  250.31 85.72 90 top
R616  1.65K  [0402]  253.99 88.77 90 top
R618  10K  [0402]  251.97 89.28 180 top
R619  10K  [0402]  251.96 91.31 0 top
R623  10K  [0402]  251.96 87.25 180 top
R625  0  [0402]  250.06 88.27 0 bottom
R627  10K  [0402]  250.06 89.28 0 bottom
R631  10  [0402]  130.18 169.16 180 top
R636  1K  [0402]  126.62 169.67 90 top
R640  1K  [0402]  125.1 170.18 0 top
R641  100K  [0402]  120.65 171.7 270 top
R642  10K  [0402]  120.14 173.23 180 top
R643  4.32K  [0402]  172.21 114.94 0 bottom
R644  39.2K  [0402]  184.66 155.45 270 bottom
R645  10K  [0402]  169.67 116.46 90 bottom
R646  10K  [0402]  170.69 115.44 270 bottom
R647  36.5K  [0402]  184.66 157.48 270 bottom
R648  10K  [0402]  186.82 151.13 0 top
R649  9.31K  [0402]  165.23 124.33 270 top
R650  10K  [0402]  167.51 126.87 0 top
R651  10K  [0402]  165.23 126.36 270 top
R652  1K  [0402]  33.78 33.4 0 top
R653  1K  [0402]  170.43 150.62 180 top
R654  1K  [0402]  54.86 60.45 270 top
R655  100  [0402]  37.72 35.81 90 top
R656  100  [0402]  170.18 143.26 0 top
R657  100  [0402]  52.83 61.47 90 top
R658  10K  [0402]  37.85 40.89 270 top
R659  10K  [0402]  172.21 143.26 180 top
R660  10K  [0402]  53.85 63.5 270 top
R661  1K  [0402]  40.26 36.32 0 top
R662  1K  [0402]  169.67 138.68 90 top
R663  1K  [0402]  50.29 67.18 180 top
R664  10K  [0402]  40.26 35.31 0 top
R665  10K  [0402]  169.67 140.72 270 top
R666  10K  [0402]  50.29 66.17 180 top
R667  1K  [0402]  53.47 52.96 270 top
R668  100  [0402]  52.45 52.96 90 top
R669  10K  [0402]  51.94 54.48 180 top
R670  1K  [0402]  51.94 56.52 180 top
R671  10K  [0402]  51.94 55.5 180 top
R672  1K  [0402]  44.45 145.29 180 top
R673  100  [0402]  34.54 143.89 90 top
R674  100  [0402]  34.04 147.32 0 top
R675  10K  [0402]  27.94 147.57 0 top
R676  10K  [0402]  34.04 149.35 0 top
R677  1K  [0402]  27.94 145.54 0 top
R678  10K  [0402]  29.46 145.03 90 top
R679  4.7K  [0402]  29.08 37.72 90 top
R680  100  [0402]  29.59 39.24 0 top
R681  10K  [0402]  28.19 45.47 0 top
R682  10K  [0402]  30.61 44.96 270 top
R683  1K  [0402]  31.62 44.96 270 top
R684  1K  [0402]  110.49 155.83 90 bottom
R685  10K  [0402]  110.49 157.86 270 bottom
R686  0  [1206]  258.7 193.42 0 top
R687  0  [1206]  258.7 174.37 0 top
R688  510  [0402]  36.58 9.53 0 top
R689  510  [0402]  32.64 9.53 0 top
R690  0  [1206]  258.7 183.9 0 top
R691  10K  [0402]  60.58 83.82 270 top
R692  1K  [0402]  60.58 85.85 90 top
R693  0  [1206]  258.7 202.95 0 top
R694  1K  [0402]  55.75 83.31 270 top
R695  10K  [0402]  58.8 80.26 180 top
R696  10K  [0402]  58.8 81.28 0 top
R697  4.7K  [0402]  12.07 22.73 0 top
R698  4.7K  [0402]  18.16 56.39 0 top
R699  100  [0402]  14.48 21.72 180 top
R700  4.7K  [0402]  10.8 26.03 90 top
R701  3.74K  [0402]  18.16 55.37 180 top
R702  4.7K  [0402]  7.11 37.85 0 top
R703  100  [0402]  7.11 23.75 90 top
R704  4.7K  [0402]  20.19 56.39 180 top
R705  1K  [0402]  5.08 32.13 90 top
R706  100K  [0402]  5.59 23.24 180 top
R707  100K  [0402]  6.6 31.62 180 top
R708  150  [0402]  208.28 98.04 180 top
R709  150  [0402]  208.28 99.31 180 top
R710  0  [0402]  133.35 52.45 90 top
R711  0  [0402]  133.1 54.48 90 top
R712  0  [0402]  150.24 61.34 270 top
R713  0  [0402]  150.75 59.82 0 top
R714  0  [0402]  132.33 52.45 90 top
R715  0  [0402]  132.08 54.48 90 top
R716  0  [0402]  150.75 62.87 0 top
R717  0  [0402]  151.26 61.34 270 top
R718  1K  [0402]  146.43 67.06 270 top
R719  1K  [0402]  251.59 59.82 180 top
R720  100  [0402]  253.62 61.72 90 top
R721  10K  [0402]  255.65 61.72 90 top
R722  1K  [0402]  251.71 67.06 0 top
R723  10K  [0402]  251.71 66.04 0 top
R724  75  [0603]  242.57 18.29 90 bottom
R725  75  [0603]  245.49 18.29 90 bottom
R726  75  [0603]  248.41 18.29 90 bottom
R727  4.7K  [0402]  254.76 50.8 90 top
R728  4.7K  [0402]  254.76 52.83 90 top
R729  4.7K  [0402]  254.76 54.86 270 top
R730  75  [0603]  251.46 18.29 90 bottom
R731  4.7K  [0402]  251.59 57.15 270 top
R732  4.7K  [0402]  253.11 56.64 180 top
R733  510  [0402]  238.38 54.61 180 top
R734  510  [0402]  238.38 53.59 180 top
R735  4.7K  [0402]  240.79 53.09 180 top
R736  4.7K  [0402]  240.79 54.1 0 top
R737  4.7K  [0402]  238.89 52.07 270 top
R738  4.7K  [0402]  240.79 55.12 0 top
R739  0  [0402]  240.79 52.07 180 top
R740  4.7K  [0402]  249.43 56.64 180 top
R741  0  [0402]  240.79 51.05 0 top
R742  15  [0402]  241.68 44.58 180 bottom
R743  2.49K  [0402]  240.79 50.04 0 top
R744  12.1K  [0402]  254.76 47.37 270 top
R745  0  [0402]  243.97 53.47 270 bottom
R746  75  [0603]  260.99 18.29 90 bottom
R747  75  [0603]  263.91 18.29 90 bottom
R748  75  [0603]  266.83 18.29 90 bottom
R749  4.7K  [0402]  277.62 50.8 90 top
R750  4.7K  [0402]  277.62 52.83 90 top
R751  4.7K  [0402]  277.62 54.86 270 top
R752  75  [0603]  269.88 18.29 90 bottom
R753  4.7K  [0402]  274.45 57.15 270 top
R754  4.7K  [0402]  275.97 56.64 180 top
R755  510  [0402]  261.24 54.61 180 top
R756  510  [0402]  261.24 53.59 180 top
R757  4.7K  [0402]  263.65 53.09 180 top
R758  4.7K  [0402]  263.65 54.1 0 top
R759  4.7K  [0402]  261.75 52.07 270 top
R760  4.7K  [0402]  263.65 55.12 0 top
R761  0  [0402]  263.65 52.07 180 top
R762  0  [0402]  263.65 51.05 0 top
R763  4.7K  [0402]  272.29 56.64 180 top
R764  15  [0402]  264.54 44.58 180 bottom
R765  2.49K  [0402]  263.65 50.04 0 top
R766  12.1K  [0402]  277.62 47.37 270 top
R767  0  [0402]  266.83 53.47 270 bottom
R768  0  [0402]  93.09 14.35 270 top
R769  0  [0402]  92.08 14.35 270 top
R770  0  [0402]  90.93 14.22 270 top
R771  0  [0402]  89.92 14.22 270 top
R772  0  [0402]  88.77 14.22 270 top
R773  0  [0402]  87.76 14.22 270 top
R774  0  [0402]  86.61 14.86 270 top
R775  0  [0402]  85.6 14.86 270 top
SW1  SWITCH_DIP_8  [CON_SWITCH_X8]  50.42 133.6 90 top
SW2  SWITCH_DIP_8  [CON_SWITCH_X8]  63.12 133.6 90 top
SW3  SWITCH_DIP_8  [CON_SWITCH_X8]  75.82 133.6 90 top
SW4  SWITCH  [CON_SW_60X60_2P2_34]  16.52 2.52 0 top
SW5  SWITCH  [CON_SW_60X60_2P2_34]  7.02 2.52 0 top
T1  H5008  [MAG_H5008]  125.86 31.88 180 top
T2  H5008  [MAG_H5008]  141.61 38.61 180 top
T3  H5008  [MAG_H5008]  161.04 26.8 180 top
T4  H5008  [MAG_H5008]  211.84 37.85 180 top
T5  H5008  [MAG_H5008]  180.09 37.85 180 top
T6  H5008  [MAG_H5008]  180.09 59.44 180 top
T7  H5008  [MAG_H5008]  211.84 59.44 180 top
T8  H5008  [MAG_H5008]  195.96 37.85 180 top
T9  H5008  [MAG_H5008]  227.71 37.85 180 top
T10  H5008  [MAG_H5008]  195.96 59.44 180 top
T11  H5008  [MAG_H5008]  227.71 59.44 180 top
T12  H5008  [MAG_H5008]  246 26.8 180 top
T13  H5008  [MAG_H5008]  264.41 26.8 180 top
TP1  -  [TP]  126.36 95.41 180 bottom
TP2  -  [TP]  98.04 125.73 0 top
TP3  -  [TP]  142.37 96.21 180 bottom
TP4  -  [TP]  143.97 94.61 180 bottom
TP5  -  [TP]  140.07 95.81 180 bottom
TP6  -  [TP]  143.17 95.41 180 bottom
TP7  -  [TP]  154.18 95 180 bottom
TP8  -  [TP]  154.18 93.98 180 bottom
TP9  -  [TP]  154.18 92.96 180 bottom
TP10  -  [TP]  140.77 97.01 180 bottom
TP11  -  [TP]  139.17 103.42 180 bottom
TP12  -  [TP]  140.77 103.42 180 bottom
TP13  -  [TP]  139.17 106.62 180 bottom
TP14  -  [TP]  140.77 106.62 180 bottom
TP15  -  [TP]  65.6 88.39 0 top
TP16  -  [TP]  65.6 86.8 0 top
TP17  -  [TP]  67.18 88.39 0 top
TP18  -  [TP]  67.18 86.8 0 top
TP19  -  [TP]  220.22 141.48 0 top
U1  T1040  [BGA_P080_780]  134.37 102.62 90 top
U2  74LVC16373  [TSSOP_48W]  97.54 119.13 0 bottom
U3  JS28F00AM29EWHA  [TSOP1_56]  80.26 120.9 180 top
U4  MT29F8G08ABBCAH4:C  [BGA_P080_NAND_63]  61.85 120.27 0 top
U5  74LVC1G86  [SC70_5]  78.61 112.14 90 top
U6  74LVC1G86  [SC70_5]  71.5 112.14 90 top
U7  74LVC1G86  [SC70_5]  75.06 112.14 90 top
U8  MT25QL512ABA1ESF-0SIT  [SO_16L]  261.49 152.15 270 top
U9  N25Q512A13GF840F  [WSON_8]  261.49 152.15 0 top
U10  RClamp0524J.TCT  [TVS_SLP2710P8]  44.58 35.81 180 bottom
U11  RClamp0524J.TCT  [TVS_SLP2710P8]  32.64 35.81 180 bottom
U12  PCA9546APW  [TSSOP_16]  225.04 169.42 180 top
U13  FXLP34P5X  [SC70_5]  95.44 77.91 90 top
U16  PI3PCIE3212  [QFN_P050_D040_B450X250_20_E3X1]  186.31 97.79 270 top
U17  PI3PCIE3212  [QFN_P050_D040_B450X250_20_E3X1]  217.68 100.08 270 top
U18  PI3PCIE3212  [QFN_P050_D040_B450X250_20_E3X1]  223.01 120.14 0 top
U19  MAX1558H  [DFN_P050_D040_B300_10_E230X150]  62.36 33.91 270 top
U20  VBUS054B-HSF  [TVS_LLP75_6L]  69.85 19.05 0 bottom
U21  74CBTLV3253  [TSSOP_16]  83.57 57.91 0 top
U22  74CBTLV3253  [TSSOP_16]  95.76 45.72 0 top
U23  74CBTLV3253  [TSSOP_16]  95.76 51.82 0 top
U24  74CBTLV3253  [TSSOP_16]  105.79 47.04 0 top
U25  74LVC125A  [TSSOP_14]  85.22 45.72 0 top
U26  74CBTLV3253  [TSSOP_16]  105.79 53.14 0 top
U27  74CBTLV3253  [TSSOP_16]  105.71 59 0 top
U28  74CBTLV3253  [TSSOP_16]  85.09 51.82 0 top
U29  MAX3232  [TSSOP_16]  113.67 38.23 90 top
U30  MAX3232  [TSSOP_16]  105.28 38.48 90 top
U31  DS1339U-33+  [MSOP_8]  51.94 147.19 0 top
U32  AT24C256  [SO_8]  73.53 60.83 0 top
U33  LCDA15C-8  [SO_16]  114.3 25.78 0 top
U34  ADT7461  [MSOP_8]  113.16 109.09 180 bottom
U35  CH7301C  [QFP_P050_64]  89.66 35.18 0 top
U36  CM2020  [TSSOP_38]  89.15 21.46 270 top
U37  DS90C387R  [QFP_P050_100]  67.95 48.39 270 top
U38  NKE0505SC  [SIP4_2P54_11X6]  237.62 153.8 180 top
U39  74CBTLV3257  [TSSOP_16]  94.36 57.91 0 top
U40  ISO1176DW  [SOIC16_1P27_7P6X10P5]  249.56 152.15 90 top
U41  74LVC1G14  [SC70_5]  249.56 143 0 top
U42  RTL8211E-VB  [QFN_P040_D040_B600_48_E440]  124.84 49.53 90 top
U45  RTL8211E-VL  [QFN_P040_D040_B600_48_E440]  142.75 57.53 90 top
U48  RTL8211DN  [QFN_P040_D040_B1000_88_E600]  162.43 48.01 90 top
U51  F104S8A  [QFN_VSC8514]  188.34 83.57 180 top
U52  F104S8A  [QFN_VSC8514]  220.09 83.57 180 top
U57  EPM570GF256  [BGA_P100_256]  45.47 95.89 0 top
U58  ICS843004-01  [TSSOP_24]  202.95 97.41 0 top
U60  IR3475  [QFN_SUPIRBUCK_4X5]  69.98 97.03 270 top
U61  74CBTLV1G125  [SC70_5]  65.28 92.08 0 top
U62  INA220A  [MSOP_10]  74.55 88.14 0 top
U64  IR3475  [QFN_SUPIRBUCK_4X5]  187.83 145.41 90 top
U65  IR3473  [QFN_SUPIRBUCK_4X5]  35.95 60.96 270 top
U66  IR3473  [QFN_SUPIRBUCK_4X5]  31.75 161.93 0 top
U67  IR3473  [QFN_SUPIRBUCK_4X5]  244.73 74.54 180 top
U68  IR3475  [QFN_SUPIRBUCK_4X5]  34.42 49.78 270 top
U69  IR3473  [QFN_SUPIRBUCK_4X5]  247.39 89.66 90 top
U72  TPS51200  [DFN_P050_D040_B300_10_E240X165]  123.7 172.97 180 top
U73  MIC47100YMME  [MSOP_8_E170]  171.2 117.47 270 top
U74  TPS73701_SOT223  [SOT223_5]  183.77 155.57 90 top
U75  MIC47100YMME  [MSOP_8_E170]  169.16 124.33 180 top
U76  MIC811  [SOT143]  13.21 25.27 180 top
U77  74LVC2G74  [U8]  6.48 29.72 180 top
U78  74AHC1G14  [SC70_5]  5.72 26.67 0 top
U79  IDT9FGV0641  [QFN_P040_D040_B500_40_E370]  239.52 130.56 90 top
U80  74LVC1G66  [SC70_5]  144.53 66.67 0 top
U81  74LVC1G66  [SC70_5]  141.73 67.82 0 top
U82  RTL8211DN  [QFN_P040_D040_B1000_88_E600]  248.03 49.91 90 top
U83  RTL8211DN  [QFN_P040_D040_B1000_88_E600]  270.89 49.91 90 top
X1  100MHz,+/-50ppm  [OSC_7X5_4]  34.29 126.75 0 top
X2  66.66MHz,+/-50ppm  [OSC_7X5_4]  34.29 134.87 0 top
X3  24MHz,+/-50ppm  [OSC_7X5_4]  34.29 118.62 0 top
X4  32.768KHz  [OSC_32X25_4]  25.78 98.17 0 top
Y1  32.768KHz  [CRY_69X14_4]  47.37 143.64 270 top
Y2  25MHz  [CRY_32X25_4]  117.09 50.67 270 top
Y3  25MHz  [CRY_32X25_4]  134.87 58.42 270 top
Y4  25MHz  [CRY_32X25_4]  151.77 47.24 180 top
Y7  25MHz  [CRY_32X25_4]  204.6 91.19 0 top
Y8  25MHz  [CRY_32X25_4]  238.38 123.83 0 top
Y9  25MHz  [CRY_32X25_4]  237.36 49.15 180 top
Y10  25MHz  [CRY_32X25_4]  260.22 49.15 180 top
Z1  -  [FIDUCIAL]  274.96 15.11 0 top
Z2  -  [FIDUCIAL]  274.96 15.11 180 bottom
Z3  -  [FIDUCIAL]  14.48 11.18 0 top
Z4  -  [FIDUCIAL]  14.48 11.18 180 bottom
Z5  -  [FIDUCIAL]  274.19 198.63 0 top
Z6  -  [FIDUCIAL]  274.19 198.63 180 bottom
Z7  -  [FIDUCIAL]  14.1 199.64 0 top
Z8  -  [FIDUCIAL]  14.1 199.64 180 bottom
Z9  MH_M8  [MH_900C400N_M]  90.04 140.72 0 top
Z10  MH_M8  [MH_900C400N_M]  278.52 203.52 0 top
Z11  MH_M8  [MH_900C400N_M]  8.52 203.52 0 top
Z12  MH_M8  [MH_900C400N_M]  143.52 203.52 0 top
Z13  MH_M8  [MH_900C400N_M]  8.52 16.02 0 top
Z14  MH_M8  [MH_900C400N_M]  158.5 60.07 0 top
Z15  MH_M8  [MH_900C400N_M]  278.52 113.02 0 top
Z16  MH_M8  [MH_900C400N_M]  278.52 8.52 0 top
Z17  MH  [MH_680C320P]  82.3 199.14 0 top
Z18  MH  [MH_680C320P]  209.3 199.14 0 top

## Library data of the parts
C1 C2 C15 C87-C91 C221 C375 C391 C755 C773 C774 C781-C784 C787-C794 C841-C843 C864 C870 C885 C886 C925 C926 C930 C931 C952-C954 C975 C976 C1065 C1066 C1085 C1098 C1119 C1132 = CAP: signal model: DEFAULT_CAPACITOR_2.2e+07pF_2_1
C5-C10 C14 C17 C18 C21 C23-C26 C28-C32 C34 C35 C39-C43 C45 C47-C52 C57-C68 C84 C86 C93-C96 C99-C106 C109-C117 C119-C121 C131 C133 C136 C147 C148 C150-C156 C170 C171 C176 C177 C179 C180 C182-C185 C190 C191 C194 C196-C208 C210-C220 C231 C232 C247 C248 C252-C256 C271-C275 C280-C288 C293 C295 C297 C306 C311 C313-C323 C325-C327 C329 C336 C344 C346-C351 C353-C355 C357-C359 C361 C366-C368 C376-C378 C381-C390 C392 C393 C395 C396 C398-C400 C403-C407 C410 C411 C414-C419 C423-C431 C435-C439 C441-C443 C445 C448-C456 C459-C462 C464 C468-C476 C480-C482 C486-C488 C490-C497 C504-C511 C518-C525 C532-C539 C549 C554 C555 C742-C749 C762 C780 C801 C803 C806 C808 C811 C812 C815 C818-C821 C828-C833 C837-C839 C847 C853 C855-C858 C891 C893-C898 C916-C919 C933 C935 C940 C941 C961 C964 C997-C999 C1011-C1013 C1018-C1022 C1025-C1036 C1045-C1048 C1050-C1052 C1054 C1055 C1067-C1069 C1071 C1076 C1077 C1086-C1097 C1099-C1103 C1105 C1110 C1111 C1120-C1131 C1133-C1137 = CAP: signal model: DEFAULT_CAPACITOR_100000pF_2_1
C22 C69 C71 C72 C74-C83 C85 C134 C139 C163-C169 C226-C230 C296 C298 C299 C301 C310 C328 C330 C332 C333 C342 C360 C362-C364 C371 C397 C544 C545 C548 C550 C552 C553 C737 C751 C753 C761 C770 C799 C804 C809 C813 C823 C827 C835 C871 C875 C876 C878 C920-C923 C932 C938 C945 C947 C957 C977 C995 C996 C1004-C1010 C1023 C1024 C1037-C1039 C1070 C1072-C1074 C1104 C1106-C1108 = CAP: signal model: DEFAULT_CAPACITOR_10000pF_2_1
C27 C33 C36 C38 C44 C46 C135 C238-C241 C258 C263 C268 C270 C402 C413 C422 C434 C440 C447 C458 C463 C467 C479 C484 C485 C558-C560 C760 C796 C800 C805 C810 C814 C844-C846 C854 C859 C862 C899-C903 C912-C915 C928 C929 C944 C946 C950 C951 C968 C972 C974 C992 C1015 C1016 C1053 = CAP: signal model: DEFAULT_CAPACITOR_1e+06pF_2_1
C55 C56 C132 C300 C303 C331 C802 C807 = CAP: signal model: DEFAULT_CAPACITOR_10.000000pF_2_1
C70 C73 C1041 = CAP_E: signal model: DEFAULT_CAPACITOR_10000pF_2_1
C92 C125 C128 C130 C137 C140-C146 C175 C178 C181 C186-C189 C195 C234 C237 C257 C262 C267 C269 C401 C412 C420 C421 C432 C433 C444 C446 C457 C465 C466 C477 C478 C483 C489 C556 C557 C750 C752 C754 C757 C771 C772 C797 C822 C826 C834 C836 C880 C888-C890 C904-C911 C1017 C1040 C1042 C1049 = CAP: signal model: DEFAULT_CAPACITOR_1e+07pF_2_1
C97 C98 C108 C118 C123 C138 C149 C161 C162 C173 C174 C242 C243 C249 C250 C798 = CAP: signal model: DEFAULT_CAPACITOR_2.2e+06pF_2_1
C107 C122 C172 C244 C251 C259 C264 C764 = CAP: signal model: DEFAULT_CAPACITOR_3000pF_2_1
C124 C127 = CAP: signal model: DEFAULT_CAPACITOR_1e+08pF_2_1
C126 C129 C294 C302 C309 C334 C341 C345 C352 C365 C374 C408 C498 C499 C512 C513 C526 C527 C541 C542 C766 C786 C887 C1075 C1078 C1081 C1084 C1109 C1112 C1115 C1118 = CAP: signal model: DEFAULT_CAPACITOR_1000pF_2_1
C192 = CAP_3T_4P: signal model: DEFAULT_CAPACITOR_100000pF_2_1
C193 C1014 = CAP_3T_4P
C233 = CAP: signal model: DEFAULT_CAPACITOR_1500pF_2_1
C245 C246 C1044 = CAP_E: signal model: DEFAULT_CAPACITOR_100000pF_2_1
C260 C265 C312 C324 C343 C356 C394 C551 C795 C865 = CAP: signal model: DEFAULT_CAPACITOR_4.7e+06pF_2_1
C261 C266 C850 C851 C934 C936 C937 C939 C960 = CAP: signal model: DEFAULT_CAPACITOR_4.7e+07pF_2_1
C276-C279 C289-C292 C778 = CAP: signal model: DEFAULT_CAPACITOR_100.000000pF_2_1
C304 C305 C339 C372 C373 C379 C380 C409 C739 C740 C1082 C1083 C1116 C1117 = CAP: signal model: DEFAULT_CAPACITOR_27.000000pF_2_1
C307 C308 C337 C338 C369 C370 C500-C503 C514-C517 C528-C531 C540 C543 C546 C547 C1079 C1080 C1113 C1114 = CAP: signal model: DEFAULT_CAPACITOR_470.000000pF_2_1
C738 C741 = CAP: signal model: DEFAULT_CAPACITOR_33.000000pF_2_1
C756 C763 C765 C769 C779 C785 = CAP: signal model: DEFAULT_CAPACITOR_220000pF_2_1
C758 = CAP_E: signal model: DEFAULT_CAPACITOR_2.2e+07pF_2_1
C759 C775 = CAP: signal model: DEFAULT_CAPACITOR_2.2e+08pF_2_1
C767 C768 C776 C777 = CAP: signal model: DEFAULT_CAPACITOR_4.7e+08pF_2_1
C816 C817 = CAP: signal model: DEFAULT_CAPACITOR_4.700000pF_2_1
C824 C825 = CAP: signal model: DEFAULT_CAPACITOR_2.000000pF_2_1
C840 C924 = CAP: signal model: DEFAULT_CAPACITOR_330000pF_2_1
C848 C849 = CAP_E: signal model: DEFAULT_CAPACITOR_4.7e+08pF_2_1
C852 C942 = CAP: signal model: DEFAULT_CAPACITOR_510.000000pF_2_1
C867 C927 C948 C949 = CAP: signal model: DEFAULT_CAPACITOR_470000pF_2_1
